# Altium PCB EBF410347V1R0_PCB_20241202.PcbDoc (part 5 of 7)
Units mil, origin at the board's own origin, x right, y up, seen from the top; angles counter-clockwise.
Board outline 5098.43 x 3464.57 mil, 6 copper layers (TOP, GND02, ART03, ART04, PWR05, BOTTOM), stack 47.2 mil thick; 566 components, 452 nets, 1905 pads, 1432 vias.
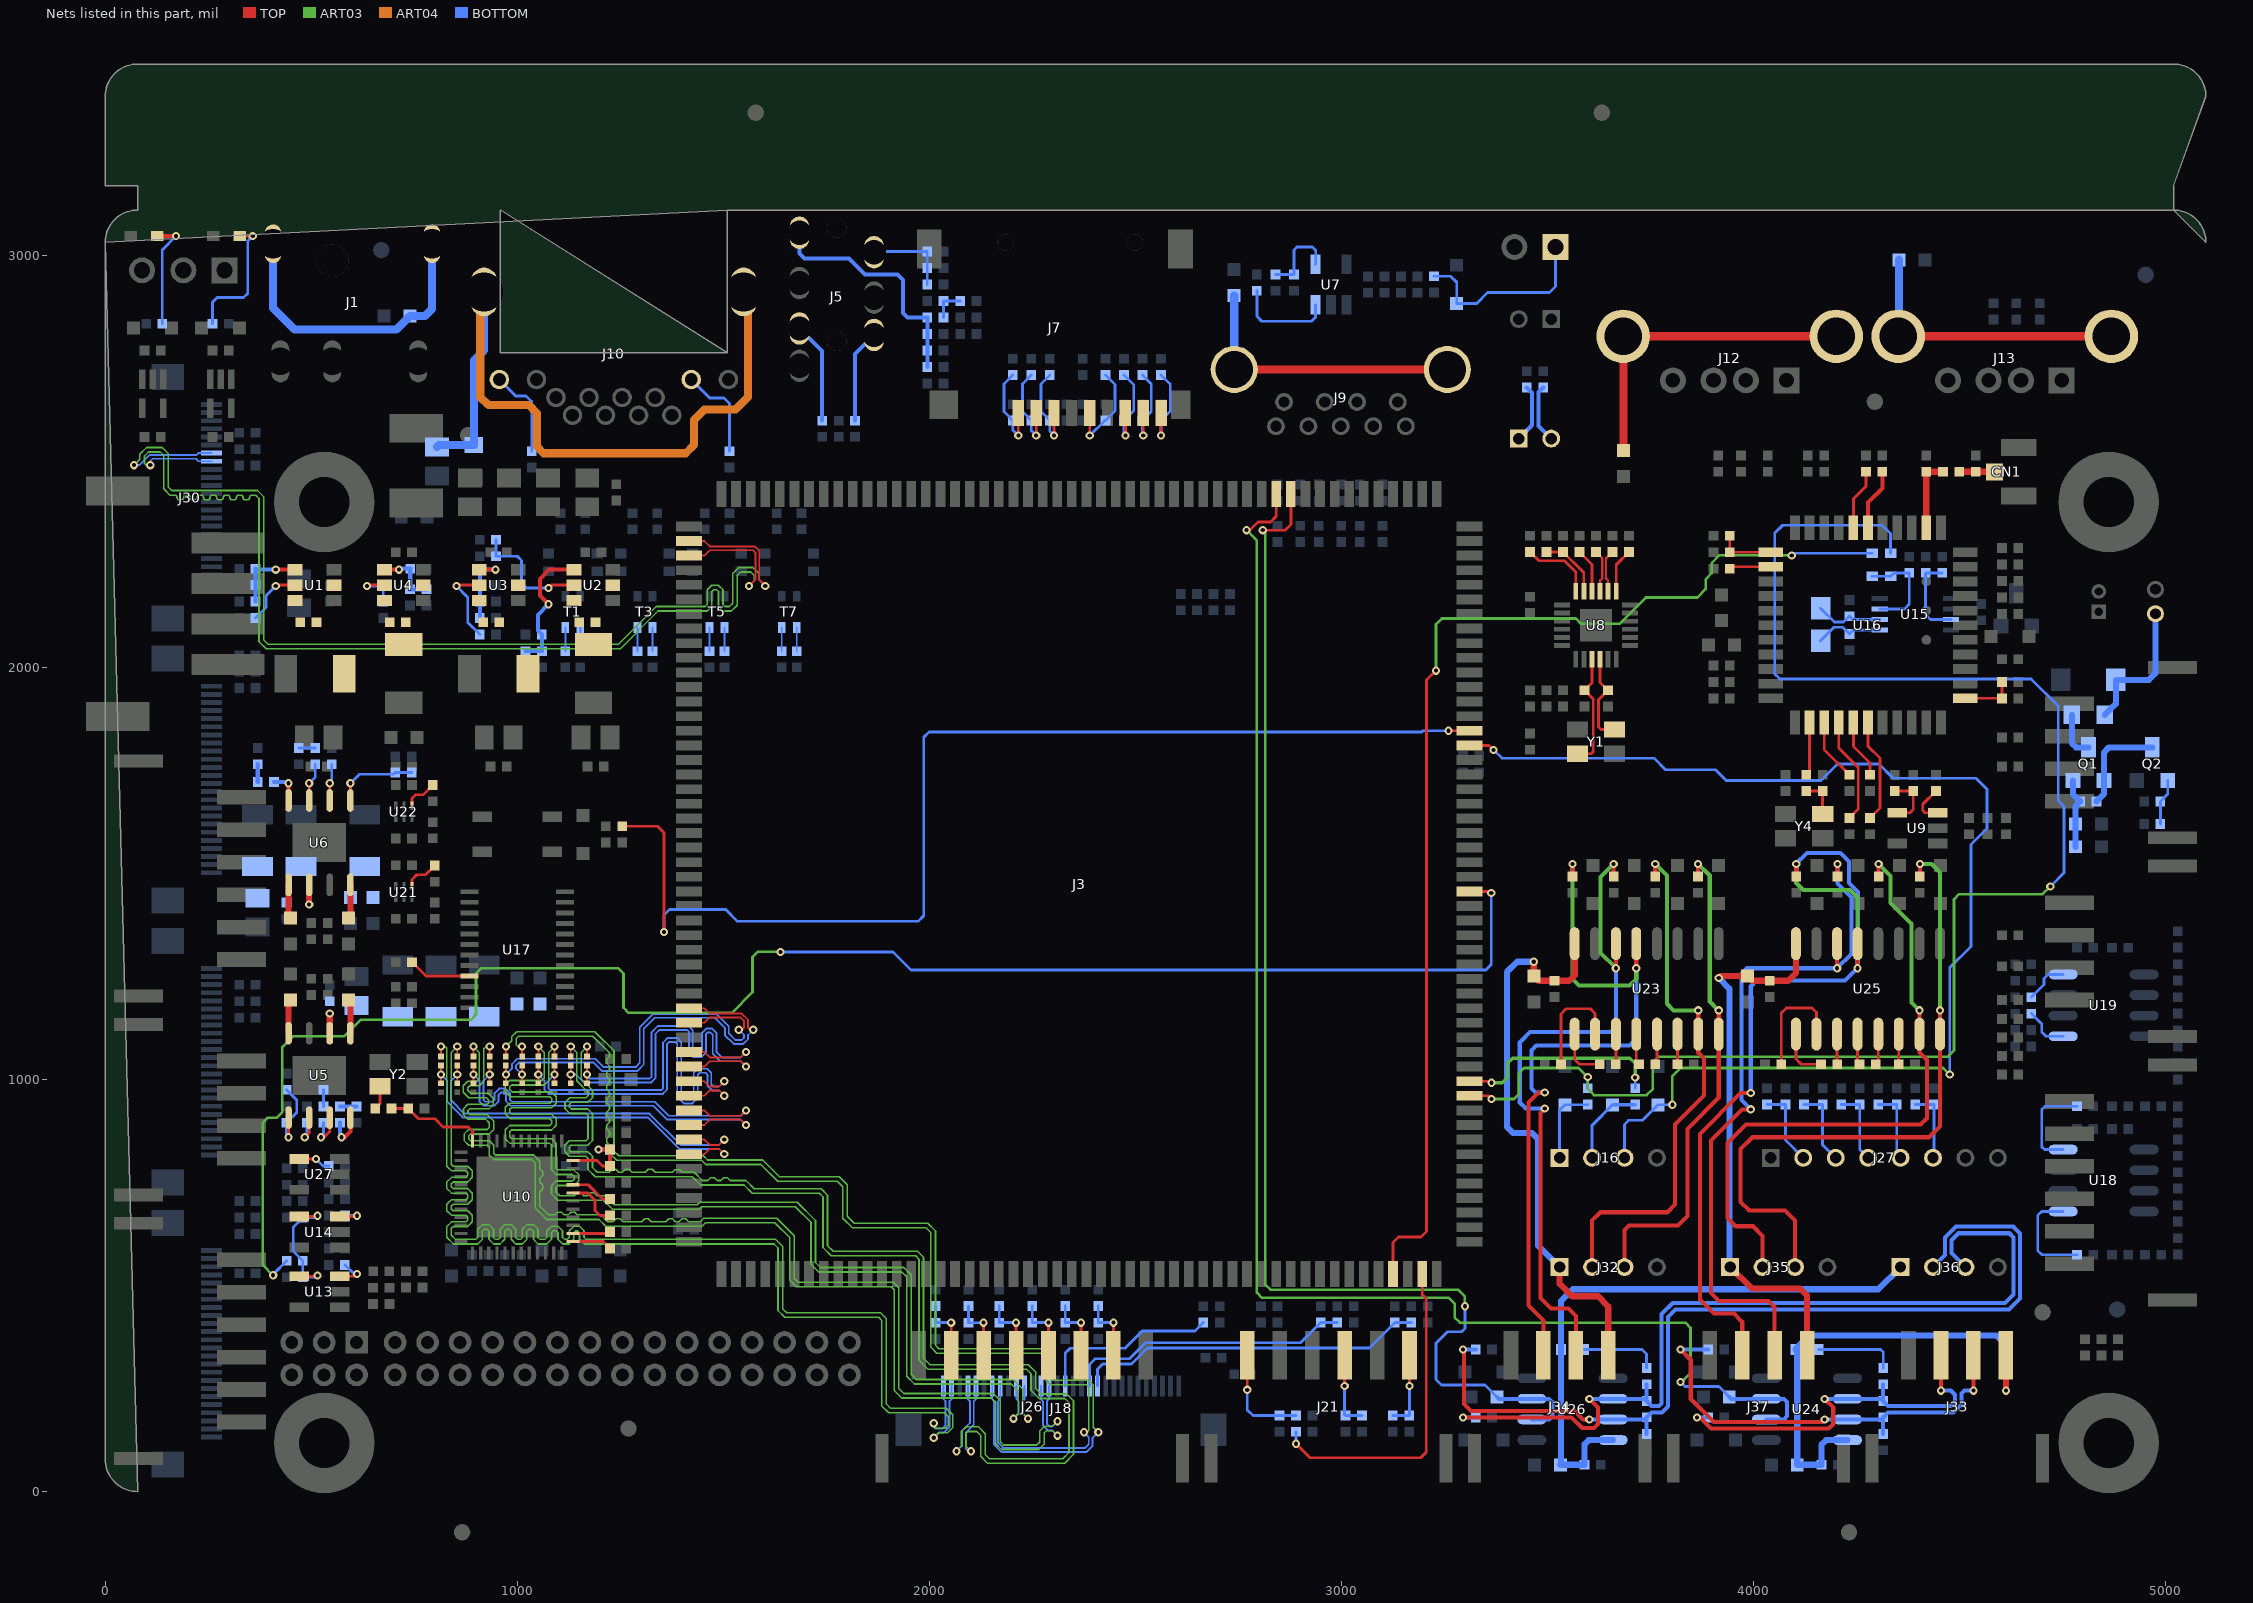
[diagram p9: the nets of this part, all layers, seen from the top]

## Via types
v1: diameter 20, hole 10, TOP to BOTTOM, 1432 vias

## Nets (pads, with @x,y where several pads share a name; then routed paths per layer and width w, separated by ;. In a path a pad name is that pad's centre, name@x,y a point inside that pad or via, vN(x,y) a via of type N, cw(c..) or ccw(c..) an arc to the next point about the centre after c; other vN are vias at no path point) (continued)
MIPI_CSI_RX1_D3N: J3.103 J30.8 | length 2705.2
  TOP w4.5: J3.103@1416.89,2271.61 1454.32,2271.61 1467.29,2284.58 1572.42,2284.58 1578,2279 1578,2213.37 v1(1562.63,2198)
  ART03 w4: v1(109.42,2491.05) 99.35,2491.05 95.24,2495.16 95.24,2513.24 105,2523 134,2523 142,2515 142,2433.64 157.24,2418.4 168.64,2418.4 cw(c168.64,2412.6) 174.44,2412.6 ccw(c180.24,2412.6) 180.24,2406.8 184.64,2406.8 ccw(c184.64,2412.6) 190.44,2412.6 cw(c196.24,2412.6) 196.24,2418.4 200.64,2418.4 cw(c200.64,2412.6) 206.44,2412.6 ccw(c212.24,2412.6) 212.24,2406.8 216.64,2406.8 ccw(c216.64,2412.6) 222.44,2412.6 cw(c228.24,2412.6) 228.24,2418.4 232.64,2418.4 cw(c232.64,2412.6) 238.44,2412.6 ccw(c244.24,2412.6) 244.24,2406.8 248.64,2406.8 ccw(c248.64,2412.6) 254.44,2412.6 cw(c260.24,2412.6) 260.24,2418.4 264.64,2418.4 cw(c264.64,2412.6) 270.44,2412.6 ccw(c276.24,2412.6) 276.24,2406.8 280.64,2406.8 ccw(c280.64,2412.6) 286.44,2412.6 cw(c292.24,2412.6) 292.24,2418.4 296.64,2418.4 cw(c296.64,2412.6) 302.44,2412.6 ccw(c308.24,2412.6) 308.24,2406.8 312.64,2406.8 ccw(c312.64,2412.6) 318.44,2412.6 cw(c324.24,2412.6) 324.24,2418.4 328.64,2418.4 cw(c328.64,2412.6) 334.44,2412.6 ccw(c340.24,2412.6) 340.24,2406.8 344.64,2406.8 ccw(c344.64,2412.6) 350.44,2412.6 cw(c356.24,2412.6) 356.24,2418.4 365.24,2418.4 373.4,2410.24 373.4,2062.8 390.6,2045.6 1250.4,2045.6 1341.8,2137 1461.18,2137 1472.31,2148.13 1472.31,2184.31 1477,2189 1483.63,2189 1488.31,2184.31 1488.31,2148.13 1499.44,2137 1519.56,2137 1534,2151.44 1534,2223.44 1542.19,2231.63 1567,2231.63 1576,2222.63 1576,2211.37 v1(1562.63,2198)
  BOTTOM w4.5: v1(109.42,2491.05) 109.42,2501.15 114.78,2506.5 220.44,2506.5 226.39,2500.55 J30.8@257.91,2500.55
MIPI_CSI_RX1_D3P: J3.102 J30.7 | length 2709
  TOP w4.5: J3.102@1416.89,2307.05 1454.32,2307.05 1467.29,2294.08 1576.36,2294.08 1587.5,2282.94 1587.5,2212.5 v1(1602,2198)
  ART03 w4: v1(70.06,2491.05) 84.24,2505.24 84.24,2517.8 100.44,2534 138.56,2534 153,2519.56 153,2438.2 161.8,2429.4 369.8,2429.4 384.4,2414.8 384.4,2067.36 395.16,2056.6 1245.84,2056.6 1337.24,2148 1456.63,2148 1461.31,2152.69 1461.31,2188.87 1472.44,2200 1488.18,2200 1499.31,2188.87 1499.31,2152.69 1504,2148 1515,2148 1523,2156 1523,2228 1537.63,2242.63 1571.56,2242.63 1587,2227.19 1587,2213 v1(1602,2198)
  BOTTOM w4.5: v1(70.06,2491.05) 83.05,2491.05 108,2516 222.15,2516 226.39,2520.24 J30.7@257.91,2520.24
MIPI_CTP_INT: J18.11 R81.2 R176.2 | length 849.4
  BOTTOM w6.8: J18.11@2408.58,255.91 2408.58,296.98 2421,309.4 2490.71,309.4 2529.71,348.4 3068.08,348.4 R176.2@3130,410.32 R81.2@3170,410.32
MIPI_CTP_RST: J18.12 R177.2 R182.2 | length 695.9
  BOTTOM w6.8: J18.12@2388.89,255.91 2388.89,308.6 2402.49,322.2 2485.4,322.2 2524.4,361.2 2900.88,361.2 R177.2@2950,410.32 R182.2@2990,410.32
MIPI_DSI_CLKN: J18.24 R106.2 | length 2762.8
  TOP w4.5: R106.2@972.48,1055.83 v1(972.48,1080)
  ART03 w4: v1(972.48,1080) 986.66,1094.18 986.66,1104.4 998.64,1116.37 1188.19,1116.37 1235,1069.56 1235,826 1246,815 1451.56,815 1461.89,804.66 1595.89,804.66 1636.56,764 1781.56,764 1801,744.56 1801,668 1818,651 1996.56,651 2015,632.56 2015,355 2023,347 2278,347 2290,335 2290,279.56 2299.56,270 2386,270 2398.25,257.75 2398.25,156.17 v1(2410.29,144.13)
  BOTTOM w4.5: J18.24@2152.67,255.91 2152.67,224.38 2157.5,219.55 2157.5,114.06 2175.06,96.5 2381.94,96.5 2396.5,111.06 2396.5,130.34 v1(2410.29,144.13)
MIPI_DSI_CLKP: J18.23 R105.2 | length 2745.4
  TOP w4.5: R105.2@1011.85,1055.83 v1(1011.85,1080)
  ART03 w4: v1(1011.85,1080) 1001.67,1080 997.66,1084 997.66,1099.84 1003.19,1105.37 1183.63,1105.37 1224,1065 1224,1056 1217,1049 1217,1040 1224,1033 1224,1024 1217,1017 1217,1008 1224,1001 1224,992 1217,985 1217,976 1224,969 1224,960 1217,953 1217,944 1224,937 1224,928 1217,921 1217,912 1224,905 1224,896 1217,889 1217,880 1224,873 1224,864 1217,857 1217,848 1224,841 1224,821.44 1241.44,804 1447,804 1457.34,793.66 1591.34,793.66 1632,753 1777,753 1790,740 1790,663.44 1813.44,640 1992,640 2004,628 2004,350.44 2018.44,336 2273.44,336 2279,330.44 2279,275 2295,259 2381.44,259 2387.25,253.19 2387.25,148.25 2383.13,144.13 v1(2375.21,144.13)
  BOTTOM w4.5: J18.23@2172.36,255.91 2172.36,224.38 2167,219.02 2167,118 2179,106 2378,106 2387,115 2387,132.34 v1(2375.21,144.13)
MIPI_DSI_D0N: J18.27 R88.2 | length 2847.8
  TOP w4.5: R88.2@1129.96,1055.83 v1(1129.96,1080)
  ART03 w4: v1(1129.96,1080) 1144.14,1065.82 1144.14,996.86 1171.63,969.37 1171.63,960.37 1166.94,955.68 1127.13,955.68 1116,944.55 1116,928.81 1127.13,917.68 1166.94,917.68 1171.63,913 1171.63,856.41 1166.94,851.72 1126.13,851.72 1115,840.59 1115,824.85 1126.13,813.72 1166.94,813.72 1171.63,809.04 1171.63,781.81 1189.44,764 1425,764 1445,744 1550.44,744 1570.44,724 1733,724 1742,715 1742,592.44 1762.44,572 1967,572 1975,564 1975,319 1997,297 2236,297 2247,286 2247,246 2267,226 2329,226 2339,216 2339,95 2324,80 2146,80 2136,90 2136,140.56 2119.56,157 2089.44,157 2078.25,145.81 2078.25,110.04 v1(2066.21,98)
  BOTTOM w4.5: v1(2066.21,98) 2079,110.79 2079,147 2098.5,166.5 2098.5,219.5 2093.62,224.38 J18.27@2093.62,255.91
MIPI_DSI_D0P: J18.26 R87.2 | length 2885.6
  TOP w4.5: R87.2@1169.33,1055.83 v1(1169.33,1080)
  ART03 w4: v1(1169.33,1080) 1155.14,1065.82 1155.14,1001.41 1182.63,973.93 1182.63,955.81 1171.5,944.68 1131.69,944.68 1127,940 1127,933.37 1131.69,928.68 1171.5,928.68 1182.63,917.55 1182.63,851.85 1171.5,840.72 1130.69,840.72 1126,836.04 1126,829.41 1130.69,824.72 1171.5,824.72 1182.63,813.59 1182.63,786.37 1194,775 1223.43,775 1230.43,782 1239.43,782 1246.43,775 1255.43,775 1262.43,782 1271.43,782 1278.43,775 1310.69,775 1317.69,782 1327.69,782 1334.69,775 1376.75,775 1382.75,781 1394.75,781 1400.75,775 1429.56,775 1449.56,755 1462.2,755 1469.2,762 1478.2,762 1485.2,755 1494.2,755 1501.2,762 1510.2,762 1517.2,755 1555,755 1575,735 1737.56,735 1753,719.56 1753,597 1767,583 1971.56,583 1986,568.56 1986,323.56 2001.56,308 2240.56,308 2258,290.56 2258,250.56 2271.56,237 2333.56,237 2350,220.56 2350,90.44 2328.56,69 2141.44,69 2125,85.44 2125,136 2115,146 2094,146 2089.25,141.25 2089.25,110.04 v1(2101.29,98)
  BOTTOM w4.5: v1(2101.29,98) 2095,98 2088.5,104.5 2088.5,143.06 2108,162.56 2108,219.08 2113.3,224.38 J18.26@2113.3,255.91
MIPI_DSI_D1N: J18.21 R92.2 | length 2775.8
  TOP w4.5: R92.2@1051.22,1055.83 v1(1051.22,1080)
  ART03 w4: v1(1051.22,1080) 1065.4,1065.82 1065.4,1002.31 1060.72,997.62 982.13,997.62 971,986.49 971,970.75 983.13,958.62 1078.72,958.62 1083.4,953.94 1083.4,947.31 1078.72,942.62 981.13,942.62 971,932.49 971,916.75 983.13,904.62 1078.72,904.62 1083.4,899.94 1083.4,893.31 1078.72,888.62 981.44,888.62 971,878.18 971,856.44 982.44,845 1079,845 1083,841 1083,780.82 1094.13,769.69 1133.31,769.69 1138,765 1138,758.37 1133.31,753.69 1094.13,753.69 1083,742.56 1083,722.44 1098.44,707 1209,707 1231,685 1441.56,685 1448.05,691.5 1674.95,691.5 1713,653.44 1713,551.44 1731.44,533 1933.44,533 1945,521.44 1945,280 1964,261 2199,261 2216.25,243.75 2216.25,189.04 v1(2204.21,177)
  BOTTOM w4.5: v1(2204.21,177) 2217,189.79 2217,219.11 2211.73,224.38 J18.21@2211.73,255.91
MIPI_DSI_D1P: J18.20 R91.2 | length 2787
  TOP w4.5: R91.2@1090.59,1055.83 v1(1090.59,1080)
  ART03 w4: v1(1090.59,1080) 1076.4,1065.82 1076.4,997.75 1065.28,986.62 986.69,986.62 982,981.94 982,975.31 987.69,969.62 1083.28,969.62 1094.4,958.49 1094.4,942.75 1083.28,931.62 986,931.62 982,927.62 982,921.31 987.69,915.62 1083.28,915.62 1094.4,904.49 1094.4,888.75 1083.28,877.62 986,877.62 982,873.62 982,861 987,856 1083.56,856 1094,845.56 1094,785.37 1098.69,780.69 1137.87,780.69 1149,769.56 1149,753.82 1137.87,742.69 1098.69,742.69 1094,738 1094,727 1103,718 1138.7,718 1145.7,725 1154.7,725 1161.7,718 1170.7,718 1177.7,725 1186.7,725 1193.7,718 1213.56,718 1235.56,696 1437,696 1443.5,702.5 1679.5,702.5 1724,658 1724,556 1736,544 1938,544 1956,526 1956,284.56 1968.56,272 2203.56,272 2227.25,248.31 2227.25,189.04 v1(2239.29,177)
  BOTTOM w4.5: J18.20@2231.41,255.91 2231.41,224.38 2226.5,219.47 2226.5,189.79 v1(2239.29,177)
MIPI_DSI_D2N: J18.18 R96.2 | length 2773
  TOP w4.5: R96.2@893.74,1055.83 v1(893.74,1080)
  ART03 w4: v1(893.74,1080) 907.92,1065.82 907.92,1000.76 903.24,996.07 879.91,996.07 868.78,984.94 868.78,969.2 882.26,955.73 925.34,955.73 931.03,950.04 931.03,943.73 927.03,939.73 879.91,939.73 869.47,929.28 869.47,914.51 879.91,904.07 922.93,904.07 932,895 932,883.52 927.31,878.84 882.13,878.84 871,867.71 871,851.97 882.13,840.84 927.31,840.84 932,836.15 932,816.44 942.44,806 1035.44,806 1044,797.44 1044,688.44 1071.97,660.47 1198.53,660.47 1215,644 1448.56,644 1456.68,652.13 1625.32,652.13 1661,616.44 1661,513.44 1677.44,497 1908,497 1915,490 1915,245.44 1933.44,227 2151,227 2161,217 2161,116.44 2175.44,102 2265.56,102 2279,115.44 2279,142.44 2284.31,147.75 2299.09,147.75 v1(2311.13,135.71)
  BOTTOM w4.5: J18.18@2270.78,255.91 2270.78,224.38 2275.87,219.29 2275.87,160.69 2288.06,148.5 2298.34,148.5 v1(2311.13,135.71)
MIPI_DSI_D2P: J18.17 R95.2 | length 2790
  TOP w4.5: R95.2@933.11,1055.83 v1(933.11,1080)
  ART03 w4: v1(933.11,1080) 924,1080 918.92,1074.92 918.92,996.2 907.8,985.07 884.47,985.07 879.78,980.38 879.78,973.76 886.81,966.73 929.9,966.73 942.03,954.6 942.03,939.17 931.58,928.73 884.47,928.73 880.47,924.73 880.47,919.07 884.47,915.07 927.49,915.07 943,899.56 943,878.97 931.87,867.84 886.69,867.84 882,863.15 882,856.52 886.69,851.84 931.87,851.84 943,840.71 943,821 947,817 1040,817 1055,802 1055,782.92 1062,775.92 1062,766.92 1055,759.92 1055,750.92 1062,743.92 1062,734.92 1055,727.92 1055,693 1076.53,671.47 1091.4,671.47 1097.93,678 1107.4,678 1113.93,671.47 1123.4,671.47 1129.93,678 1139.4,678 1145.93,671.47 1203.09,671.47 1219.56,655 1232.53,655 1239.53,662 1249.53,662 1256.53,655 1302.16,655 1309.16,662 1318.16,662 1325.16,655 1360.78,655 1367.78,662 1376.78,662 1383.78,655 1392.78,655 1399.78,662 1408.78,662 1415.78,655 1444,655 1452.13,663.13 1629.87,663.13 1672,621 1672,518 1682,508 1912.56,508 1926,494.56 1926,250 1938,238 2155.56,238 2172,221.56 2172,121 2180,113 2261,113 2268,120 2268,147 2279.75,158.75 2299.09,158.75 v1(2311.13,170.79)
  BOTTOM w4.5: J18.17@2290.47,255.91 2290.47,224.38 2285.37,219.29 2285.37,164.63 2292,158 2298.34,158 v1(2311.13,170.79)
MIPI_DSI_D3N: J18.30 R101.2 | length 2813.8
  TOP w4.5: R101.2@815,1055.83 v1(815,1080)
  ART03 w4: v1(815,1080) 825.18,1080 829.18,1076 829.18,789.59 840.31,778.47 875.31,778.47 880,773.78 880,767.15 875.31,762.47 840.31,762.47 829.18,751.34 829.18,735.59 840.31,724.47 875.31,724.47 880,719.78 880,713.15 875.31,708.47 840.31,708.47 829.18,697.34 829.18,681.59 840.31,670.47 875.31,670.47 880,665.78 880,659.15 875.31,654.47 840.31,654.47 829.18,643.34 829.18,617.26 845.44,601 904.36,601 915.49,612.13 915.49,632.31 920.18,637 926.8,637 931.49,632.31 931.49,612.13 942.62,601 958.36,601 969.49,612.13 969.49,632.31 974.18,637 980.8,637 985.49,632.31 985.49,612.13 996.62,601 1012.36,601 1023.49,612.13 1023.49,632.31 1028.18,637 1034.81,637 1039.49,632.31 1039.49,612.13 1050.62,601 1071.85,601 1082.98,612.13 1082.98,628.19 1087.67,632.87 1094.29,632.87 1098.98,628.19 1098.98,612.13 1110.11,601 1125.85,601 1136.98,612.13 1136.98,628.19 1141.35,632.55 1147,632.55 1151,628.55 1151,612.44 1162.44,601 1623,601 1633,591 1633,439.44 1649.44,423 1877,423 1885,415 1885,207.84 1901.44,191.4 2036.6,191.4 2046.17,181.83 2046.17,160.17 2039.75,153.75 2014.87,153.75 2010.87,157.75 v1(2010.87,165.79)
  BOTTOM w4.5: v1(2010.87,165.79) 2010.87,159.13 2017,153 2032,153 2039.5,160.5 2039.5,219.44 2034.56,224.38 J18.30@2034.56,255.91
MIPI_DSI_D3P: J18.29 R100.2 | length 2833.4
  TOP w4.5: R100.2@854.37,1055.83 v1(854.37,1080)
  ART03 w4: v1(854.37,1080) 840.18,1065.82 840.18,794.15 844.87,789.47 879.87,789.47 891,778.34 891,762.59 879.87,751.47 844.87,751.47 840.18,746.78 840.18,740.15 844.87,735.47 879.87,735.47 891,724.34 891,708.59 879.87,697.47 844.87,697.47 840.18,692.78 840.18,686.15 844.87,681.47 879.87,681.47 891,670.34 891,654.59 879.87,643.47 844.87,643.47 840.18,638.78 840.18,621.82 850,612 899.8,612 904.49,616.69 904.49,636.87 915.62,648 931.36,648 942.49,636.87 942.49,616.69 947.18,612 953.8,612 958.49,616.69 958.49,636.87 969.62,648 985.36,648 996.49,636.87 996.49,616.69 1001.18,612 1007.8,612 1012.49,616.69 1012.49,636.87 1023.62,648 1039.36,648 1050.49,636.87 1050.49,616.69 1055.18,612 1067.29,612 1071.98,616.69 1071.98,632.74 1083.11,643.87 1098.85,643.87 1109.98,632.74 1109.98,616.69 1114.67,612 1121.29,612 1125.98,616.69 1125.98,632.74 1136.79,643.55 1151.56,643.55 1162,633.11 1162,617 1167,612 1627.56,612 1644,595.56 1644,444 1654,434 1881.56,434 1896,419.56 1896,212.4 1906,202.4 2041.16,202.4 2057.17,186.39 2057.17,155.61 2044.31,142.75 2022.91,142.75 v1(2010.87,130.71)
  BOTTOM w4.5: v1(2010.87,130.71) 2023.66,143.5 2035.93,143.5 2049,156.56 2049,219.13 2054.25,224.38 J18.29@2054.25,255.91
MIPI_DSI_TX_CLKN: J3.135 R106.1 R107.1 | length 992.5
  TOP w4.5: R107.1@972.48,990.83 v1(972.48,1012.5) R106.1@972.48,1034.17 ; J3.135@1416.89,1137.76 1454.32,1137.76 1467.29,1150.72 1540.84,1150.72 1550.5,1141.06 1550.5,1125.44 1546,1120.94 v1(1537.71,1120.94)
  BOTTOM w4.5: v1(972.48,1012.5) 987.41,1027.43 987.41,1037.73 1000.18,1050.5 1189.5,1050.5 1209.84,1030.16 1287.16,1030.16 1297.5,1040.5 1297.5,1126.94 1330.06,1159.5 1483.5,1159.5 1513.5,1129.5 1513.5,1111.94 1529.44,1096 1544.72,1096 1550.5,1101.78 1550.5,1108.14 v1(1537.71,1120.94)
MIPI_DSI_TX_CLKP: J3.134 R104.1 R105.1 | length 1008.2
  TOP w4.5: R104.1@1011.85,990.83 v1(1011.85,1012.5) R105.1@1011.85,1034.17 ; J3.134@1416.89,1173.19 1454.32,1173.19 1467.29,1160.22 1544.78,1160.22 1560,1145 1560,1125.44 1564.5,1120.94 v1(1572.79,1120.94)
  BOTTOM w4.5: v1(1011.85,1012.5) 996.91,1027.43 996.91,1033.8 1004.12,1041 1185.56,1041 1205.9,1020.66 1291.1,1020.66 1307,1036.57 1307,1123 1334,1150 1479.56,1150 1504,1125.56 1504,1108 1525.5,1086.5 1548.66,1086.5 1560,1097.84 1560,1108.14 v1(1572.79,1120.94)
MIPI_DSI_TX_D0N: J3.138 R88.1 R89.1 | length 910
  TOP w4.5: R89.1@1129.96,990.83 v1(1129.96,1012.5) R88.1@1129.96,1034.17 ; J3.138@1416.89,1031.46 1454.32,1031.46 1467.29,1044.42 1542.21,1044.42 v1(1555,1031.63)
  BOTTOM w4.5: v1(1129.96,1012.5) 1141.39,1012.5 1160.82,993.07 1325.44,993.07 1335.5,1003.13 1335.5,1110.5 1345.57,1120.57 1412,1120.57 1416.5,1116.07 1416.5,1065.06 1426.56,1055 1447.94,1055 1458,1065.06 1458,1109.63 1462.64,1114.27 1469,1114.27 1474.5,1108.77 1474.5,1062.39 1492.47,1044.42 1542.21,1044.42 v1(1555,1031.63)
MIPI_DSI_TX_D0P: J3.137 R86.1 R87.1 | length 869.9
  TOP w4.5: R86.1@1169.33,990.83 v1(1169.33,1012.5) R87.1@1169.33,1034.17 ; J3.137@1416.89,1066.89 1454.32,1066.89 1467.29,1053.92 1542.21,1053.92 v1(1555,1066.71)
  BOTTOM w4.5: v1(1169.33,1012.5) 1169.33,1007.07 1173.83,1002.57 1321.5,1002.57 1326,1007.07 1326,1114.44 1341.63,1130.07 1415.94,1130.07 1426,1120 1426,1069 1430.5,1064.5 1444,1064.5 1448.5,1069 1448.5,1113.57 1458.7,1123.77 1472.94,1123.77 1484,1112.71 1484,1066.33 1496.4,1053.92 1542.21,1053.92 v1(1555,1066.71)
MIPI_DSI_TX_D1N: J3.140 R92.1 R93.1 | length 981.6
  TOP w4.5: R93.1@1051.22,990.83 v1(1051.22,1012.5) R92.1@1051.22,1034.17 ; J3.140@1416.89,960.59 1454.32,960.59 1467.29,973.56 1489.62,973.56 v1(1502.41,960.77)
  BOTTOM w4.5: v1(1051.22,1012.5) 1066.15,997.57 1066.15,975.06 1076.22,965 1353.44,965 1363.5,975.06 1363.5,1086 1369,1091.5 1384,1091.5 1388.5,1087 1388.5,958.06 1404.56,942 1425,942 1438.07,955.06 1438.07,1012.07 1442.57,1016.57 1457,1016.57 1461.5,1012.07 1461.5,985.12 1473.06,973.56 1489.62,973.56 v1(1502.41,960.77)
MIPI_DSI_TX_D1P: J3.139 R90.1 R91.1 | length 965.9
  TOP w4.5: R90.1@1090.59,990.83 v1(1090.59,1012.5) R91.1@1090.59,1034.17 ; J3.139@1416.89,996.02 1454.32,996.02 1467.29,983.06 1489.62,983.06 v1(1502.41,995.85)
  BOTTOM w4.5: v1(1090.59,1012.5) 1075.65,997.57 1075.65,979 1080.15,974.5 1349.5,974.5 1354,979 1354,1089.94 1365.06,1101 1387.94,1101 1398,1090.94 1398,962 1408.5,951.5 1421.07,951.5 1428.57,959 1428.57,1016 1438.63,1026.07 1460.94,1026.07 1471,1016 1471,989.06 1477,983.06 1489.62,983.06 v1(1502.41,995.85)
MIPI_DSI_TX_D2N: J3.142 R96.1 R97.1 | length 979.2
  TOP w4.5: R97.1@893.74,990.83 v1(893.74,1012.5) R96.1@893.74,1034.17 ; J3.142@1416.89,889.72 1454.32,889.72 1467.29,902.69 1542.21,902.69 v1(1555,889.9)
  BOTTOM w4.5: v1(893.74,1012.5) 908.67,997.57 908.67,946.56 918.74,936.5 943.85,936.5 954.69,947.34 954.69,963.23 959.96,968.5 967.41,968.5 972.69,963.23 972.69,947.34 983.52,936.5 1330.06,936.5 1363.81,902.75 1542.15,902.75 v1(1555,889.9)
MIPI_DSI_TX_D2P: J3.141 R94.1 R95.1 | length 963.4
  TOP w4.5: R94.1@933.11,990.83 v1(933.11,1012.5) R95.1@933.11,1034.17 ; J3.141@1416.89,925.16 1454.32,925.16 1467.29,912.19 1542.21,912.19 v1(1555,924.98)
  BOTTOM w4.5: v1(933.11,1012.5) 918.17,997.57 918.17,950.5 922.67,946 939.91,946 945.19,951.27 945.19,967.16 956.02,978 971.35,978 982.19,967.16 982.19,951.27 987.46,946 1334,946 1367.75,912.25 1542.27,912.25 v1(1555,924.98)
MIPI_DSI_TX_D3N: J3.144 R101.1 R102.1 | length 937.5
  TOP w4.5: R102.1@815,990.83 v1(815,1012.5) R101.1@815,1034.17 ; J3.144@1416.89,818.86 1454.32,818.86 1467.29,831.83 1489.62,831.83 v1(1502.41,819.03)
  BOTTOM w4.5: v1(815,1012.5) 829.93,997.57 829.93,945.63 867.56,908 1317,908 1393.18,831.82 1489.62,831.82 v1(1502.41,819.03)
MIPI_DSI_TX_D3P: J3.143 R99.1 R100.1 | length 921.8
  TOP w4.5: R99.1@854.37,990.83 v1(854.37,1012.5) R100.1@854.37,1034.17 ; J3.143@1416.89,854.29 1454.32,854.29 1467.29,841.33 1489.62,841.33 v1(1502.41,854.12)
  BOTTOM w4.5: v1(854.37,1012.5) 839.43,997.57 839.43,949.56 871.5,917.5 1320.94,917.5 1397.11,841.32 1489.62,841.32 v1(1502.41,854.12)
MIPI_LCD_PWR_EN: J3.25 R179.1 | length 4173.7
  TOP w6.8: J3.25@3310.59,1456.65 3360.06,1456.65 v1(3364,1452.72)
  ART03 w6.3: v1(407.72,525) 382,550.72 382,895 394,907 416,907 430,921 430,1079 456,1105 580,1105 620,1145 887.4,1145 900,1157.6 900,1257.4 912.6,1270 1245.4,1270 1258,1257.4 1258,1174.6 1270.6,1162 1521,1162 1571,1212 1571,1297.14 1583.6,1309.74 v1(1639,1309.74)
  BOTTOM w6.8: v1(407.72,525) 407.72,527.4 R179.1@440.32,560 ; v1(1639,1309.74) 1912.26,1309.74 1956,1266 3350.4,1266 3364,1279.6 v1(3364,1452.72)
MIPI_LCD_RST: J18.15 R186.2 | length 445.9
  BOTTOM w6.8: J18.15@2329.84,255.91 2329.84,335.84 2342,348 2475,348 2517,390 2644.68,390 R186.2@2665,410.32
N16722097: C10.1 U2.6
N16722109: C10.2 L3.1 U2.2
N16722129: C12.1 R5.1 R9.1 U2.4 | length 331
  TOP w10: v1(1076,2153.63) 1055,2174.63 1055,2215 1077.4,2237.4 U2.4@1137.76,2237.4
  BOTTOM w10: R5.1@1020,2039.68 C12.1@1060,2039.68 1059.68,2040 R9.1@1059.68,2080 1050,2089.68 1050,2127.63 v1(1076,2153.63)
N16722243: R7.1 R8.1 U2.5 | length 296.1
  TOP w6.8: v1(1076,2193) 1083,2200 U2.5@1137.76,2200
  BOTTOM w6.8: R8.1@948.68,2310 R7.1@948.68,2270 1000,2270 1010,2260 1010,2204.97 1021.97,2193 v1(1076,2193)
N16722849: J1.1 J1.5 L2.1 | length 742.8
  BOTTOM w20: J1.1@407.48,3028.61 407.48,2872.52 460,2820 706.5,2820 L2.1@739.5,2853 776,2853 793.28,2870.28 J1.5@793.28,3028.61
N16722969: C25.1 R14.1 R17.1 U4.4 | length 154.1
  TOP w10: U4.4@677.76,2237.4 v1(713,2237.4)
  BOTTOM w10: v1(713,2237.4) 715.6,2240 R17.1@740.32,2240 740.32,2190 R14.1@740,2189.68 C25.1@780,2189.68
N16722987: C22.2 L5.1 U4.2
N16723079: C22.1 U4.6
N16723587: C1.1 U1.6
N16723611: C1.2 L1.1 U1.2
N16723631: C2.1 R1.1 R4.1 U1.4 | length 177.2
  TOP w10: v1(413.82,2237.4) U1.4@460.76,2237.4
  BOTTOM w10: R1.1@364.68,2160 C2.1@364.68,2200 R4.1@364.68,2240 367.28,2237.4 v1(413.82,2237.4)
N16724039: R10.1 U3.5 | length 197.6
  TOP w6.8: v1(852.52,2198.03) 854.49,2200 U3.5@907.76,2200
  BOTTOM w6.8: v1(852.52,2198.03) 852.52,2197.48 880,2170 880,2109.32 R10.1@909.32,2080
N16724119: C11.1 U3.6
N16724131: C11.2 L4.1 U3.2
N16724163: C15.1 R6.1 R11.1 U3.4 | length 189.6
  TOP w10: U3.4@907.76,2237.4 v1(947,2237.4)
  BOTTOM w10: C15.1@909.32,2120 R6.1@909.32,2160 R11.1@909.32,2200 909.32,2229.32 917.4,2237.4 v1(947,2237.4)
N16724623: LED2.2 R13.2 | length 323
  TOP w6.8: LED2.2@326.19,3047.24 v1(358.24,3047.24)
  BOTTOM w6.8: R13.2@260.32,2834.37 260.32,2886.32 272,2898 336,2898 346,2908 346,3035 v1(358.24,3047.24)
N16724791: LED1.2 R12.2 | length 272.5
  TOP w10: LED1.2@126.19,3047.24 v1(172,3047.24)
  BOTTOM w6.8: R12.2@138.68,2834.37 138.68,3013.92 v1(172,3047.24)
N16783121: D7.1 J7.1 R43.2 | length 225
  TOP w6.8: v1(2216.15,2563) J7.1@2216.15,2618.11
  BOTTOM w6.8: R43.2@2202.61,2709.69 2181.41,2688.49 2181.41,2620.89 D7.1@2202.61,2599.69 2202.61,2576.54 v1(2216.15,2563)
N16783123: D3.1 J7.7 R47.2 | length 222.9
  TOP w6.8: v1(2476,2563) J7.7@2475.99,2618.11
  BOTTOM w6.8: R47.2@2472.61,2709.69 2496.41,2685.89 2496.41,2623.49 D3.1@2472.61,2599.69 2472.61,2566.39 v1(2476,2563)
N16783125: D4.1 J7.5 R46.2 | length 237.6
  TOP w6.8: v1(2389.38,2563) J7.5@2389.38,2618.11
  BOTTOM w6.8: v1(2389.38,2563) 2426.07,2599.69 D4.1@2427.61,2599.69 2450.61,2622.69 2450.61,2686.69 R46.2@2427.61,2709.69
N16783127: D5.1 J7.3 R45.2 | length 223.9
  TOP w6.8: v1(2302.77,2563) J7.3@2302.76,2618.11
  BOTTOM w6.8: R45.2@2292.61,2709.69 2270.97,2688.05 2270.97,2621.33 D5.1@2292.61,2599.69 2292.61,2573.16 v1(2302.77,2563)
N16783129: D6.1 J7.2 R44.2 | length 224.3
  TOP w6.8: v1(2259.46,2563) J7.2@2259.46,2618.11
  BOTTOM w6.8: R44.2@2247.61,2709.69 2226.41,2688.49 2226.41,2620.89 D6.1@2247.61,2599.69 2247.61,2574.85 v1(2259.46,2563)
N16783131: D2.1 J7.8 R48.2 | length 220.1
  TOP w6.8: v1(2519.3,2563) J7.8@2519.3,2618.11
  BOTTOM w6.8: R48.2@2517.61,2709.69 2538.81,2688.49 2538.81,2620.89 D2.1@2517.61,2599.69 2517.61,2564.69 v1(2519.3,2563)
N16783147: D1.1 J7.9 R49.2 | length 220
  TOP w6.8: v1(2562.61,2563) J7.9@2562.61,2618.11
  BOTTOM w6.8: v1(2562.61,2563) D1.1@2562.61,2599.69 2584.61,2621.69 2584.61,2687.69 R49.2@2562.61,2709.69
N16783231: J6.1 R41.2 | length 142.9
  BOTTOM w10: J6.1@3430.63,2555.55 3463,2587.92 3463,2666.69 R41.2@3450,2679.69
N16783233: J6.2 R42.2 | length 141.3
  BOTTOM w10: R42.2@3490,2679.69 3479,2668.69 3479,2585.92 J6.2@3509.37,2555.55
N16783279: C28.1 C29.1 C30.1 C31.1 C32.1 R19.2 R21.2 U5.6 | length 47.6
  TOP w15: U5.6@545,1112.36 v1(545,1160)
N16783471: C41.1 C42.1 C43.1 C44.1 C45.1 R30.2 R32.2 U6.6 | length 47.6
  TOP w15: v1(495,1425) U6.6@495,1472.64
N16783658: R25.2 R28.1 U5.1 | length 185.9
  TOP w6.8: v1(445,860) U5.1@445,907.64
  BOTTOM w6.8: R28.1@440,975.32 465,950.32 465,920 440.32,895.32 R25.2@440,895.32 440,865 v1(445,860)
N16783744: R22.2 U5.4 | length 97.6
  TOP w10: v1(573.74,860) 581,860 595,874 U5.4@595,907.64
  BOTTOM w10: R22.2@570,895.32 570,863.74 v1(573.74,860)
N16783769: R24.2 U5.3 | length 98.8
  TOP w6.8: v1(523.74,860) 531.4,860 545,873.6 U5.3@545,907.64
  BOTTOM w6.8: v1(523.74,860) 530,866.26 R24.2@530,895.32
N16783771: C34.2 R22.1 | length 40
  BOTTOM w10: R22.1@570,934.68 C34.2@610,934.68
N16783785: C35.2 R24.1 | length 40.6
  BOTTOM w6.8: R24.1@530,934.68 C35.2@530,975.32
N16783804: L7.1 U5.8 | length 83.2
  TOP w15: U5.8@445,1112.36 445,1188.5 L7.1@450,1193.5
N16783806: L6.1 U5.5 | length 83.2
  TOP w15: L6.1@590,1193.5 595,1188.5 U5.5@595,1112.36
N16783823: C39.1 U5.2 | length 89.7
  TOP w6.8: v1(484.37,860) 495,870.63 U5.2@495,907.64
  BOTTOM w6.8: v1(484.37,860) 490,865.63 C39.1@490,895.32
N16783940: R39.2 R40.1 U6.1 | length 201.5
  TOP w6.8: U6.1@595,1677.36 v1(595,1719)
  BOTTOM w6.8: v1(595,1719) 617,1741 699.68,1741 R40.1@704,1745.32 R39.2@744,1745.32
N16784027: R35.2 U6.4 | length 78.2
  TOP w10: U6.4@445,1677.36 v1(445,1719)
  BOTTOM w10: R35.2@409.68,1722 442,1722 v1(445,1719)
N16784039: R37.2 U6.3 | length 94.2
  TOP w6.8: U6.3@495,1677.36 v1(495,1719)
  BOTTOM w6.8: v1(495,1719) 510,1734 R37.2@510,1765.32
N16784051: C46.2 R35.1 | length 43.5
  BOTTOM w10: C46.2@370,1765.32 370.32,1765 R35.1@370.32,1722
N16784053: C47.2 R37.1 | length 40
  BOTTOM w6.8: C47.2@470,1804.68 R37.1@510,1804.68
N16784084: L9.1 U6.8 | length 83.2
  TOP w15: L9.1@590,1391.5 595,1396.5 U6.8@595,1472.64
N16784086: L8.1 U6.5 | length 83.2
  TOP w15: U6.5@445,1472.64 445,1396.5 L8.1@450,1391.5
N16784100: C51.1 U6.2 | length 90
  TOP w6.8: U6.2@545,1677.36 v1(545,1719)
  BOTTOM w6.8: v1(545,1719) 550,1724 C51.1@550,1765.32
N16784225: C50.1 J5.6 R31.1 R36.1 | length 210
  BOTTOM w6.8: J5.6@1865.98,3007.87 1867.48,3009.37 C50.1@1995.32,3009.37 R31.1@1995.32,2969.37 R36.1@1995.32,2929.37
N16784316: C36.1 J5.1 R20.2 R23.1 R26.1 | length 592.2
  BOTTOM w10: J5.1@1684.88,3055.12 1684.88,3004.49 1697,2992.37 1805,2992.37 1844,2953.37 1923,2953.37 1936,2940.37 1936,2860.37 1947,2849.37 R20.2@1995.32,2849.37 R26.1@1995.32,2809.37 C36.1@1995.32,2769.37 R23.1@1995.32,2729.37
N16784333: C33.1 R18.1 R20.1 | length 80.6
  BOTTOM w6.8: R20.1@2034.68,2849.37 C33.1@2034.68,2889.37 R18.1@2075.32,2889.37
N16784429: J5.3 R34.1 | length 246.6
  BOTTOM w10: J5.3@1684.88,2822.83 1740,2767.72 R34.1@1740,2599.05
N16784431: J5.4 R33.1 | length 227.1
  BOTTOM w10: R33.1@1820,2599.05 1820,2761.1 J5.4@1865.98,2807.09
N16786732: R2.1 R3.1 U4.5 | length 123.8
  TOP w6.8: v1(635.67,2198.03) 637.64,2200 U4.5@677.76,2200
  BOTTOM w6.8: v1(635.67,2198.03) 672.71,2198.03 R2.1@675,2200.32 R3.1@675,2159.68
N16786936: R15.1 U1.5 | length 146.1
  TOP w6.8: v1(413.82,2198.03) 415.79,2200 U1.5@460.76,2200
  BOTTOM w6.8: R15.1@364.68,2120 390,2145.32 390,2174.21 v1(413.82,2198.03)
N16788412: C54.2 T1.4 | length 57.4
  BOTTOM w4.5: C54.2@1116.79,2039.68 T1.4@1116.79,2097.11
N16788414: C55.2 T1.1 | length 57.4
  BOTTOM w4.5: C55.2@1153.21,2039.68 T1.1@1153.21,2097.11
N16788463: C56.2 T3.4 | length 57.4
  BOTTOM w4.5: C56.2@1291.79,2039.68 T3.4@1291.79,2097.11
N16788475: C57.2 T3.1 | length 57.4
  BOTTOM w4.5: C57.2@1328.21,2039.68 T3.1@1328.21,2097.11
N16788524: C58.2 T5.4 | length 57.4
  BOTTOM w4.5: C58.2@1466.79,2039.68 T5.4@1466.79,2097.11
N16788526: C59.2 T5.1 | length 57.4
  BOTTOM w4.5: C59.2@1503.21,2039.68 T5.1@1503.21,2097.11
N16788585: C60.2 T7.4 | length 57.4
  BOTTOM w4.5: C60.2@1641.79,2039.68 T7.4@1641.79,2097.11
N16788587: C61.2 T7.1 | length 57.4
  BOTTOM w4.5: C61.2@1678.21,2039.68 T7.1@1678.21,2097.11
N16792936: J10.9 R16.1 | length 221.3
  BOTTOM w6.8: J10.9@956.57,2698.82 996.39,2659 1021.4,2659 1035,2645.4 R16.1@1035,2524.68
N16792940: C62.2 J10.13 J10.14 R51.2 | length 1838.1
  ART04 w20: J10.13@919.56,2911.42 910,2901.86 910,2657 930,2637 1028,2637 1048,2617 1048,2536 1064,2520 1409,2520 1429,2540 1429,2601 1454,2626 1530,2626 1560,2656 1560,2900.9 J10.14@1549.48,2911.42
  BOTTOM w20: C62.2@805,2535.04 809.96,2540 R51.2@895,2540 895,2745 919.56,2769.56 J10.13@919.56,2911.42
N16793616: J10.11 R50.1 | length 232.6
  BOTTOM w6.8: J10.11@1422.32,2698.82 1467.14,2654 1501.4,2654 1515,2640.4 R50.1@1515,2524.68
N16801073: J9.10 J9.11 L10.2 | length 697
  TOP w20: J9.11@2740.19,2723.24 J9.10@3257.51,2723.24
  BOTTOM w20: L10.2@2740,2902.87 2740,2723.43 J9.11@2740.19,2723.24
N16801211: C65.1 R56.2 U7.4 | length 197.5
  BOTTOM w6.8: R56.2@2840,2954.05 C65.1@2885,2954.05 2885,3013.37 2892,3020.37 2930,3020.37 2938,3012.37 2938,2978.99 U7.4@2937.6,2978.58
N16801228: R57.1 U7.3 | length 244.1
  BOTTOM w6.8: R57.1@2795,2914.69 2795,2852.37 2807,2840.37 2928,2840.37 2937.6,2849.97 U7.3@2937.6,2880.16
N16802593: D23.1 J11.1 R193.1 | length 465
  BOTTOM w6.8: R193.1@3225,2949.68 3265.32,2949.68 3280,2935 D23.1@3280,2883.74 3328.74,2883.74 3355,2910 3505,2910 3520,2925 J11.1@3520,3020.55
N16803235: R64.1 U8.15 | length 103.4
  TOP w5.2: R64.1@3618.11,2280.32 3633.09,2265.33 3633.09,2216.15 3627.95,2211 U8.15@3627.95,2185.24
N16803237: R65.1 U8.14 | length 103.7
  TOP w5.2: U8.14@3647.64,2185.24 3647.64,2211 3642.49,2216.15 3642.49,2264.7 R65.1@3658.11,2280.32
N16803510: C73.1 U8.3 Y1.1 | length 281.3
  TOP w6.8: Y1.1@3572.83,1790.47 3606.3,1790.47 3611.31,1795.48 3611.31,1923.48 C73.1@3590.11,1944.68 3608.27,1962.84 U8.3@3608.27,2019.88
N16803514: C74.1 U8.4 Y1.3 | length 223.7
  TOP w6.8: U8.4@3627.95,2019.88 3627.95,1963.84 C74.1@3647.11,1944.68 3624.11,1921.68 3624.11,1855.29 3629.87,1849.53 Y1.3@3663.39,1849.53
N16803540: R66.1 U8.13 | length 107.8
  TOP w6.8: U8.13@3667.32,2185.24 3667.32,2249.53 R66.1@3698.11,2280.32
N16803549: C72.1 R61.1 U8.17 | length 156
  TOP w6.8: R61.1@3498.11,2280.32 C72.1@3538.11,2280.32 3588.58,2229.85 U8.17@3588.58,2185.24
N16803553: R63.1 U8.16 | length 107.6
  TOP w6.8: R63.1@3578.11,2280.32 3608.27,2250.16 U8.16@3608.27,2185.24
N16803559: R62.1 U8.18 | length 177.2
  TOP w6.8: R62.1@3458.11,2280.32 3479.31,2259.12 3541.21,2259.12 3568.9,2231.43 U8.18@3568.9,2185.24
N16804913: J12.5 J12.6 L11.2 | length 795
  TOP w20: L11.2@3685,2526.5 3685,2802.64 J12.6@3683.93,2803.7 J12.5@4201.27,2803.7
N16810803: C77.1 R67.2 U9.4 | length 132.7
  TOP w6.8: R67.2@4343.11,1700.32 C77.1@4388.11,1700.32 4388.11,1655 4380.51,1647.4 U9.4@4348.9,1647.4
N16810815: R68.1 U9.3 | length 99.3
  TOP w6.8: R68.1@4443.11,1700.32 4411,1668.21 4411,1653 4416.6,1647.4 U9.3@4447.32,1647.4
N16816847: D33.1 J16.2 R72.1 | length 204.5
  BOTTOM w8: J16.2@3608.58,810 3608.58,889.21 D33.1@3658.11,938.73 3712.52,938.73 R72.1@3713.11,939.32
N16816849: D32.1 J16.1 R71.1 | length 189.5
  BOTTOM w6.8: J16.1@3529.84,810 3529.84,925.47 D32.1@3543.11,938.73 3597.52,938.73 R71.1@3598.11,939.32
N16821329: C87.1 C88.1 C89.1 C90.1 U10.11 | length 231.9
  TOP w6.8: U10.11@1135.73,803.58 1193.42,803.58 1207,790 C89.1@1225.32,790
  TOP w10: v1(1197,830) C90.1@1225.32,830 C89.1@1225.32,790
  BOTTOM w10: v1(1197,830) C88.1@1225.32,830 C87.1@1225.32,790
N16823430: R83.2 R85.1 U10.24 | length 244
  TOP w6.8: R83.2@694.68,930 R85.1@735.32,930 760.32,905 800,905 820,885 881.83,885 891.63,875.2 U10.24@891.63,850.83
N16823432: R83.1 Y2.3 | length 58.2
  TOP w6.8: R83.1@655.32,930 666.72,941.4 Y2.3@666.72,983.47
N16823570: R76.2 U10.8 | length 103.9
  TOP w6.8: U10.8@1135.73,744.53 1172.47,744.53 1207,710 R76.2@1225.32,710
N16823572: R77.2 U10.7 | length 127
  TOP w6.8: U10.7@1135.73,724.84 1171.16,724.84 1188.93,707.07 1188.93,682 1200.93,670 R77.2@1225.32,670
N16823879: R74.2 U10.1 | length 96.5
  TOP w6.8: U10.1@1135.73,606.73 1208.59,606.73 R74.2@1225.32,590
N16823895: R75.2 U10.2 | length 91.1
  TOP w6.8: U10.2@1135.73,626.42 1221.74,626.42 R75.2@1225.32,630
N16825657: D53.1 J26.2 R139.1 | length 156.5
  TOP w6.8: J26.2@2446.85,331.1 v1(2446.85,410)
  BOTTOM w6.8: R139.1@2410,450.32 D53.1@2410,409.68 2410.32,410 v1(2446.85,410)
N16825664: D52.1 J26.3 R140.1 | length 157.8
  TOP w6.8: J26.3@2368.11,331.1 v1(2368.11,410)
  BOTTOM w6.8: R140.1@2330,450.32 D52.1@2330,409.68 2330.32,410 v1(2368.11,410)
N16825671: D51.1 J26.4 R141.1 | length 159
  TOP w6.8: J26.4@2289.37,331.1 v1(2289.37,410)
  BOTTOM w6.8: R141.1@2250,450.32 D51.1@2250,409.68 2250.32,410 v1(2289.37,410)
N16825678: D50.1 J26.5 R142.1 | length 160.3
  TOP w6.8: J26.5@2210.63,331.1 v1(2210.63,410)
  BOTTOM w6.8: R142.1@2170,450.32 D50.1@2170,409.68 2170.32,410 v1(2210.63,410)
N16825685: D49.1 J26.6 R143.1 | length 156.6
  TOP w6.8: J26.6@2131.89,331.1 v1(2131.89,410)
  BOTTOM w6.8: R143.1@2095,450.32 D49.1@2095,409.68 2131.57,409.68 v1(2131.89,410)
N16825692: D48.1 J26.7 R144.1 | length 157.8
  TOP w6.8: J26.7@2053.15,331.1 v1(2053.15,410)
  BOTTOM w6.8: R144.1@2015,450.32 D48.1@2015,409.68 2015.32,410 v1(2053.15,410)
N16827764: D59.1 J27.2 R145.1 | length 192.1
  BOTTOM w6.8: R145.1@4033.11,939.32 D59.1@4078.11,939.32 4078.11,852.91 J27.2@4121.02,810
N16827766: D58.1 J27.3 R146.1 | length 187.4
  BOTTOM w6.8: R146.1@4123.11,939.32 D58.1@4168.11,939.32 4168.11,841.65 J27.3@4199.77,810
N16827768: D57.1 J27.4 R147.1 | length 182.8
  BOTTOM w6.8: R147.1@4213.11,939.32 D57.1@4258.11,939.32 4258.11,830.39 J27.4@4278.51,810
N16827770: D56.1 J27.5 R148.1 | length 178.1
  BOTTOM w6.8: R148.1@4303.11,939.32 D56.1@4348.11,939.32 4348.11,819.13 J27.5@4357.24,810
N16827772: D55.1 J27.6 R149.1 | length 175.2
  BOTTOM w6.8: R149.1@4393.11,939.32 D55.1@4438.11,939.32 4438.11,812.12 J27.6@4435.98,810
N16832694: C114.2 C120.1 U16.2 | length 177.1
  TOP w15.5: U16.2@4419.84,2338.78 C120.1@4419.84,2475.28 4420.12,2475 C114.2@4460.32,2475
N16832701: C114.1 C115.1 CN1.1 | length 85.8
  TOP w15.5: C114.1@4499.68,2475 4539.68,2475 C115.1@4540,2475.32 4540.36,2474.96 CN1.1@4585.24,2474.96
N16832725: R156.2 U16.6 | length 151
  TOP w10: U16.6@4278.11,2338.78 4278.11,2400 4313.11,2435 R156.2@4313.11,2475.32
N16832727: R158.2 U16.7 | length 149.1
  TOP w6.8: U16.7@4242.68,2338.78 4242.68,2409.57 4273.11,2440 R158.2@4273.11,2475.32
N16832815: R164.2 R165.2 U16.12 | length 139.2
  TOP w6.8: R165.2@3942.79,2320 R164.2@3942.79,2280 3943.06,2279.73 U16.12@4041.89,2279.73
N16832856: R166.2 U16.13 | length 100.9
  TOP w6.8: R166.2@3942.79,2240 3947.08,2244.29 U16.13@4041.89,2244.29
N16833042: R162.2 R163.1 Y4.3 | length 95.9
  TOP w6.8: R162.2@4128.11,1700.32 R163.1@4168.11,1700.32 4168.11,1644.8 Y4.3@4168.39,1644.53
N16833048: R162.1 U16.24 | length 130.1
  TOP w6.8: R162.1@4128.11,1739.68 4136.38,1747.95 U16.24@4136.38,1866.34
N16833114: R151.2 R155.1 U16.34 | length 129.3
  TOP w6.8: U16.34@4514.33,1925.39 4603.04,1925.39 R151.2@4603.43,1925 R155.1@4603.43,1965
N16853010: D45.1 D46.1 R130.2 U15.3 | length 246
  BOTTOM w6.8: D45.1@4288.11,2221.42 D46.1@4333.11,2221.42 4341.38,2229.69 R130.2@4378.11,2229.69 4378.11,2153.37 4366.9,2142.16 U15.3@4306.5,2142.16
N16853145: C119.1 U15.2 Y3.2 | length 166.5
  BOTTOM w6.8: Y3.2@4163.11,2143.77 4196.51,2110.37 4218.79,2110.37 C119.1@4233.11,2124.69 4241.22,2116.57 U15.2@4306.5,2116.57
N16853170: C118.1 U15.1 Y3.1 | length 167.8
  BOTTOM w6.8: Y3.1@4163.11,2064.97 4195.71,2097.57 4216.59,2097.57 C118.1@4233.11,2081.05 4243.04,2090.98 U15.1@4306.5,2090.98
N16853193: R131.2 R135.1 U15.7 | length 207.8
  BOTTOM w6.8: R135.1@4458.11,2229.69 R131.2@4418.11,2229.69 4418.1,2128.38 4429.9,2116.57 U15.7@4479.72,2116.57
N16853900: Q1.1 Q2.3 R136.2 | length 248.6
  BOTTOM w15: R136.2@4832.79,1675 4850.61,1692.82 Q1.1@4850.61,1726 4850.61,1793.5 4863.11,1806 Q2.3@4968.11,1806
N16853902: Q2.1 R137.2 R138.1 | length 113.4
  BOTTOM w6.8: R137.2@4987.79,1620 R138.1@4987.79,1675 5005.61,1692.82 Q2.1@5005.61,1726
N16853946: D47.1 J25.1 R134.2 | length 343.2
  BOTTOM w15: R134.2@4853.11,1885 4880.04,1911.93 D47.1@4880.04,1970 4960.11,1970 4975.91,1985.8 J25.1@4975.91,2130.47
N16853981: Q1.2 R132.2 R133.2 R136.1 | length 173.3
  BOTTOM w15: Q1.2@4775.61,1726 4775.61,1692.82 R136.1@4793.43,1675 4781.61,1663.18 R132.2@4781.61,1620 R133.2@4781.61,1565
N16854018: Q1.3 R134.1 | length 113.1
  BOTTOM w15: R134.1@4773.11,1885 4773.11,1816 4783.11,1806 Q1.3@4813.11,1806
N16869660: C151.1 U25.3 | length 73.2
  TOP w6.8: C151.1@4203.31,1037 U25.3@4203.31,1110.2
N16869662: C151.2 U25.1 | length 126.3
  TOP w6.8: U25.1@4103.31,1110.2 4103.31,1049.8 4116.11,1037 C151.2@4163.95,1037
N16869664: C152.1 U25.5 | length 75.9
  TOP w6.8: C152.1@4296.79,1037 4303.31,1043.52 U25.5@4303.31,1110.2
N16869666: C152.2 U25.4 | length 75.1
  TOP w6.8: U25.4@4252.91,1110.2 4252.91,1041.52 C152.2@4257.43,1037
N16869668: C155.1 U25.6 | length 73.2
  TOP w6.8: C155.1@4352.91,1037 U25.6@4352.91,1110.2
N16869670: C154.1 U25.2 | length 272.4
  TOP w6.8: C154.1@4067.79,1037 4067.79,1161.79 4080,1174 4142,1174 4152.91,1163.09 U25.2@4152.91,1110.2
N16869989: D66.1 R119.2 | length 190.9
  BOTTOM w6.8: D66.1@3588.95,345 3730,345 3741,334 R119.2@3741,299.68
N16870097: D54.1 R109.2 | length 198.9
  BOTTOM w6.8: D54.1@4157.95,345 4309,345 4315,339 R109.2@4315,299.68
N16870438: C148.1 U23.3 | length 73.2
  TOP w6.8: C148.1@3666.31,1037 U23.3@3666.31,1110.2
N16870440: C148.2 U23.1 | length 126.9
  TOP w6.8: U23.1@3566.31,1110.2 3566.31,1048.8 3578.11,1037 C148.2@3626.95,1037
N16870442: C149.1 U23.5 | length 75.1
  TOP w6.8: C149.1@3761.79,1037 3766.31,1041.52 U23.5@3766.31,1110.2
N16870444: C149.2 U23.4 | length 75.9
  TOP w6.8: U23.4@3715.91,1110.2 3715.91,1043.52 C149.2@3722.43,1037
N16870446: C147.1 U23.6 | length 73.2
  TOP w6.8: C147.1@3815.91,1037 U23.6@3815.91,1110.2
N16870448: C146.1 U23.2 | length 265.2
  TOP w6.8: C146.1@3533.11,1037 3533.11,1159.2 3545.91,1172 3604.11,1172 3615.91,1160.2 U23.2@3615.91,1110.2
N16880008: C162.1 U27.4 | length 79.2
  TOP w6.8: U27.4@470.79,807.4 v1(511.4,807.4)
  BOTTOM w6.8: v1(511.4,807.4) 528.8,790 C162.1@542.82,790
N16948483: J13.5 J13.6 L12.2 | length 703.8
  TOP w20: J13.6@4351.57,2803.7 J13.5@4868.91,2803.7
  BOTTOM w20: J13.6@4351.57,2803.7 4353.5,2805.63 L12.2@4353.5,2989.37
N16990717: D39.1 J21.1 R98.2 | length 186.6
  TOP w6.8: v1(3165.51,256) J21.1@3165.51,331.1
  BOTTOM w6.8: R98.2@3125,184.68 D39.1@3165,184.68 3165.51,185.19 v1(3165.51,256)
N16990719: D40.1 J21.3 R103.2 | length 187.2
  TOP w6.8: v1(3008.03,256) J21.3@3008.03,331.1
  BOTTOM w6.8: v1(3008.03,256) 3008.03,186.65 D40.1@3010,184.68 R103.2@3050,184.68
N16990803: D41.1 J21.6 R108.2 | length 256.6
  TOP w6.8: v1(2771.81,247) J21.6@2771.81,331.1
  BOTTOM w6.8: v1(2771.81,247) 2771.81,198.28 2785.41,184.68 D41.1@2850,184.68 R108.2@2890,184.68
N16991546: R188.2 U17.21 | length 153.3
  TOP w6.8: R188.2@744.68,1285 778.66,1251.02 U17.21@883.86,1251.02
N17000237: R215.1 U21.4 | length 85.3
  TOP w6.8: U21.4@744.68,1469.76 744.68,1485.68 756,1497 777.32,1497 R215.1@800,1519.68
N17000272: R216.1 U22.4 | length 81.5
  TOP w6.8: U22.4@744.68,1664.76 744.68,1682.68 753,1691 771.32,1691 R216.1@795,1714.68
N17004192: C138.1 C145.1 R179.2 U13.4 U14.4 | length 328.7
  TOP w6.8: U13.4@470.79,522.4 513.03,522.4 v1(515,524.37) ; U14.4@470.79,667.4 513.03,667.4 v1(515,669.37)
  BOTTOM w6.8: v1(515,524.37) 510.63,520 C138.1@479.68,520 R179.2@479.68,560 456.23,583.45 456.23,641.23 479.68,664.68 C145.1@479.68,665 510.63,665 v1(515,669.37)
N17004200: R180.1 U13.3 | length 82.5
  TOP w6.8: U13.3@569.21,522.4 605.4,522.4 v1(611,528)
  BOTTOM w6.8: R180.1@581.68,550 582.4,550 604.4,528 v1(611,528)
N17004297: R181.1 U14.3 | length 72.5
  TOP w6.8: U14.3@569.21,667.4 609.46,667.4 v1(611.43,669.37)
  BOTTOM w6.8: R181.1@582.18,670 610.8,670 v1(611.43,669.37)
N17012559: R239.2 U18.1 | length 250.2
  BOTTOM w6.8: U18.1@4751.57,680 4700,680 4690,670 4690,585 4700,575 R239.2@4785.32,575
N17012562: R240.2 U18.4 | length 233.2
  BOTTOM w6.8: U18.4@4751.57,830 4706.8,830 4700,836.8 4700,927 4708,935 R240.2@4785.32,935
N17015515: R245.2 U19.1 | length 111.2
  BOTTOM w6.8: R245.2@4674.68,1160 4700,1134.68 4700,1115 4710,1105 U19.1@4751.57,1105
N17015527: R246.2 U19.4 | length 108.3
  BOTTOM w6.8: R246.2@4674.68,1200 4705,1230.32 4705,1245 4715,1255 U19.4@4751.57,1255
ON/OFF_KEY: D46.2 J3.11 R71.2 | length 3872.7
  TOP w6.8: J3.11@3310.59,960.59 3356.67,960.59 v1(3364.54,952.72)
  ART03 w6.3: v1(3364.54,952.72) 3418.51,952.72 3431.11,965.32 3431.11,1015.4 3443.71,1028 3575.59,1028 3597.59,1006 v1(3598.11,1006) 3598.11,976.89 3613,962 3741.11,962 3756.11,977 3756.11,1042 3769.11,1055 4471,1055 4487,1071 4487,1437.4 4499.6,1450 4702.14,1450 v1(4720.71,1468.58)
  BOTTOM w6.8: R71.2@3598.11,978.68 v1(3598.11,1006) ; D46.2@4333.11,2277.32 4333.11,2324.89 4312.63,2345.37 4071.37,2345.37 4052,2326 4052,1984 4064.2,1971.8 4674.2,1971.8 4740.11,1905.89 4740.11,1675.89 4754,1662 4754,1501.87 v1(4720.71,1468.58)
PCM_CLK: R160.1 U16.26 | length 260.2
  TOP w6.8: U16.26@4207.24,1866.34 4207.24,1804.87 4254.69,1757.42 4254.69,1656.26 R160.1@4233.11,1634.68
PCM_DIN: R159.1 U16.27 | length 143.4
  TOP w6.8: U16.27@4242.68,1866.34 4242.68,1808.43 4283.11,1768 R159.1@4283.11,1739.68
PCM_OUT: R161.1 U16.25 | length 152.1
  TOP w6.8: U16.25@4171.81,1866.34 4171.81,1800.98 R161.1@4233.11,1739.68
PCM_SYNC: R157.1 U16.28 | length 253.6
  TOP w6.8: U16.28@4278.11,1866.34 4278.11,1809 4307.11,1780 4307.11,1658.68 R157.1@4283.11,1634.68
PWM3_IR: J3.199 R108.1 | length 801.3
  TOP w6.8: v1(2890,116) 2924,82 3192.63,82 3206.23,95.6 3206.23,467.77 3196.42,477.58 J3.199@3196.42,527.52
  BOTTOM w6.8: v1(2890,116) R108.1@2890,145.32
RECOVERY/ADC_KEY: D34.1 J3.35 J16.3 | length 3038
  TOP w6.8: J3.35@3310.59,1810.98 3358.65,1810.98 v1(3369.63,1800)
  ART03 w6.3: v1(3803.38,938.73) 3803.38,1008.27 3823.11,1028 4460.51,1028 v1(4476.51,1012)
  BOTTOM w6.8: v1(3369.63,1800) 3389.63,1780 3759,1780 3787,1752 3908,1752 3934.23,1725.77 4163.77,1725.77 4203.8,1765.8 4305.05,1765.8 4339.65,1731.2 4540.31,1731.2 4566.85,1704.65 4566.85,1687.76 4566.85,1609.29 4528.11,1570.55 4528.11,1323.11 4476.51,1271.51 v1(4476.51,1012) ; J16.3@3687.32,810 3687.32,891.21 3697.11,901 3730.38,901 D34.1@3768.11,938.73 v1(3803.38,938.73)
RESET_KEY: J3.12 R72.2 | length 515.6
  TOP w6.8: J3.12@3310.59,996.02 3360.61,996.02 v1(3364.54,992.09)
  ART03 w8: v1(3364.54,992.09) 3391.09,992.09 3403.11,1004.11 3403.11,1039.4 3415.71,1052 3700.51,1052 3713.11,1039.4 v1(3713.11,1005)
  BOTTOM w6.8: R72.2@3713.11,978.68 v1(3713.11,1005)
RS232_1_3V3: C144.1 J32.1 J34.1 L14.1 U23.16 | length 1392
  TOP w15: v1(3467.11,1286) L14.1@3467.11,1251.5 3478.93,1239.68 C144.1@3517.11,1239.68 3552.79,1239.68 3566.31,1253.2 U23.16@3566.31,1329.8 ; J32.1@3529.84,545 3529.84,504 3559.84,474 3623,474 3647.95,449.05 J34.1@3647.95,331.1
  BOTTOM w15: v1(3467.11,1286) 3427,1286 3402,1261 3402,885 3417,870 3463.11,870 3478.11,855 3478.11,596.73 J32.1@3529.84,545
RS232_1_R1IN: J34.3 R116.2 U23.13 | length 1807.4
  TOP w10: J34.3@3490.47,331.1 3490.47,415.53 3454.11,451.89 3454.11,944.11 3478.79,968.79 v1(3493.75,968.79) ; R116.2@3560.91,1492.68 v1(3560.91,1523) ; v1(3715.91,1270.2) U23.13@3715.91,1329.8
  ART03 w10: v1(3560.91,1523) 3560.91,1244 3576.91,1228 3699.91,1228 3715.91,1244 v1(3715.91,1270.2)
  BOTTOM w10: v1(3493.75,968.79) 3471.11,968.79 3461.11,978.79 3461.11,1071 3473.11,1083 3699.11,1083 3715.91,1099.8 v1(3715.91,1270.2)
RS232_1_R2IN: J32.3 R113.2 U23.8 | length 1193.4
  TOP w10: J32.3@3687.32,545 3687.32,635.21 3698.11,646 3817.11,646 3840.11,669 3840.11,880 3915.91,955.8 U23.8@3915.91,1110.2 v1(3915.91,1168) ; R113.2@3865.91,1492.68 v1(3865.91,1523)
  ART03 w10: v1(3865.91,1523) 3894.11,1494.8 3894.11,1189.8 v1(3915.91,1168)
RS232_1_T1OUT: J34.2 R118.2 U23.14 | length 1638
  TOP w10: v1(3493.75,929.42) 3483.11,918.78 3483.11,469.89 3509,444 3551,444 3569.21,425.79 J34.2@3569.21,331.1 ; R118.2@3660.91,1492.68 v1(3660.91,1523) ; v1(3666.31,1270.2) U23.14@3666.31,1329.8
  ART03 w10: v1(3660.91,1523) 3629.11,1491.2 3629.11,1307.4 v1(3666.31,1270.2)
  BOTTOM w10: v1(3493.75,929.42) 3447.69,929.42 3433.11,944 3433.11,1090 3458.11,1115 3653.11,1115 3666.31,1128.2 v1(3666.31,1270.2)
RS232_1_T2OUT: J32.2 R114.2 U23.7 | length 1299.9
  TOP w10: J32.2@3608.58,545 3608.58,657.47 3629.11,678 3791.11,678 3810.11,697 3810.11,891 3880.11,961 3880.11,1051.32 3866.31,1065.12 U23.7@3866.31,1110.2 v1(3866.31,1168) ; R114.2@3761.91,1492.68 v1(3761.91,1523)
  ART03 w10: v1(3761.91,1523) 3790.11,1494.8 3790.11,1184 3806.11,1168 v1(3866.31,1168)
RS232_2_3V3: C150.1 J35.1 J37.1 L16.1 U25.16 | length 1346.8
  TOP w15: v1(3915.91,1246.74) 3920.67,1251.5 L16.1@3986,1251.5 3997.82,1239.68 C150.1@4040,1239.68 4084.68,1239.68 4103.31,1258.31 U25.16@4103.31,1329.8 ; J35.1@3943.55,545 3995.55,493 4113,493 4130.39,475.61 J37.1@4130.39,331.1
  BOTTOM w15: v1(3915.91,1246.74) 3942,1220.65 3942,546.54 J35.1@3943.55,545
RS232_2_R1IN: J37.3 R126.2 U25.13 | length 2196.7
  TOP w10: J37.3@3972.91,331.1 3972.91,412.09 3953,432 3904.11,432 3870.11,466 3870.11,868 3969.22,967.11 v1(3993.74,967.11) ; R126.2@4104.11,1492.68 v1(4104.11,1523) ; v1(4252.91,1270.2) U25.13@4252.91,1329.8
  ART03 w10: v1(4104.11,1523) 4104.11,1477 4121.11,1460 4234.11,1460 4252.91,1441.2 v1(4252.91,1270.2)
  BOTTOM w10: v1(3993.74,967.11) 3993.74,1226.4 4007.34,1240 4222.71,1240 v1(4252.91,1270.2) 4254,1271.29 4254,1455 4232,1477 4232,1529 4211,1550 4130,1550 4104.11,1524.11 v1(4104.11,1523)
RS232_2_R2IN: J35.3 R123.2 U25.8 | length 1602.5
  TOP w10: J35.3@4101.02,545 4101.02,658.09 4077.11,682 3990.11,682 3969.11,703 3969.11,831 3998.11,860 4426.78,860 4452.91,886.13 U25.8@4452.91,1110.2 v1(4452.91,1168) ; R123.2@4404.11,1492.68 v1(4404.11,1523)
  ART03 w10: v1(4404.11,1523) 4432.91,1523 4452.91,1503 v1(4452.91,1168)
RS232_2_T1OUT: J37.2 R128.2 U25.14 | length 1731.3
  TOP w10: v1(3993.74,927.74) 3972.85,927.74 3897.11,852 3897.11,482 3916.11,463 4037,463 4051.65,448.35 J37.2@4051.65,331.1 ; v1(4203.31,1270.2) U25.14@4203.31,1329.8 ; R128.2@4204.11,1492.68 v1(4204.11,1523)
  BOTTOM w10: v1(3993.74,927.74) 3971,950.48 3971,1257 3984.2,1270.2 v1(4203.31,1270.2) 4238,1304.89 4238,1442 4204.11,1475.89 v1(4204.11,1523)
RS232_2_T2OUT: J35.2 R124.2 U25.7 | length 1565.5
  TOP w10: J35.2@4022.28,545 4022.28,620.83 3999.11,644 3957.11,644 3937.11,664 3937.11,846 3982.11,891 4406.11,891 4421.11,906 4421.11,1048 4403.31,1065.8 U25.7@4403.31,1110.2 v1(4403.31,1168) ; R124.2@4304.11,1492.68 v1(4304.11,1523)
  ART03 w10: v1(4304.11,1523) 4333.11,1494 4333.11,1428.89 4384,1378 4384,1187.31 v1(4403.31,1168)
RS485_1_3V3: C153.1 D54.2 J33.1 L15.2 U24.8 | length 1188.7
  TOP w15: v1(4612.83,245) J33.1@4612.83,331.1
  BOTTOM w15: U24.8@4228.43,125 4177,125 4165.32,113.32 C153.1@4165.32,65 L15.2@4106.5,65 4106.5,340.55 D54.2@4102.05,345 4136.05,379 4590,379 4613,356 4613,245.17 v1(4612.83,245)
RS485_1_A: J33.3 R109.1 R110.2 R115.2 U24.6 | length 952.5
  TOP w10: v1(3863,180) 3870.37,180 3897.37,153 4183,153 4194,164 4194,204 v1(4173,225) ; v1(4455.35,245) J33.3@4455.35,331.1
  BOTTOM w10: v1(3863,180) R115.2@3890.32,180 ; v1(4173,225) U24.6@4228.43,225 4309.68,225 R110.2@4315,219.68 ; R109.1@4315,260.32 R110.2@4315,219.68 ; v1(4455.35,245) 4479,245 4489,235 4489,218 4479,208 4326.68,208 R110.2@4315,219.68
RS485_1_B: J33.2 R110.1 R112.1 R117.2 U24.7 | length 1080.7
  TOP w10: v1(3823,345) 3848,320 3848,225 3904,169 4167,169 v1(4173,175) ; v1(4534.09,245) J33.2@4534.09,331.1
  BOTTOM w10: v1(3823,345) R117.2@3890.32,345 ; v1(4173,175) U24.7@4228.43,175 4309.68,175 R110.1@4315,180.32 ; R112.1@4315,139.68 R110.1@4315,180.32 ; v1(4534.09,245) 4512.09,245 4505,237.91 4505,211.37 4485.63,192 4327,192 4315.32,180.32 R110.1@4315,180.32
RS485_1_DIR: J3.62 R111.1 U24.2 U24.3 | length 3619
  TOP w6.8: v1(2769.86,2333.28) 2778.28,2333.28 2798,2353 2828,2353 2842.09,2367.09 J3.62@2842.09,2421.22
  ART03 w6.3: v1(2769.86,2333.28) 2795,2308.14 2795,482.6 2807.6,470 3261,470 3275,456 3275,422.6 3287.6,410 3834.88,410 3847.48,397.4 3847.48,287.74 3826,266.26 v1(3823,266.26)
  BOTTOM w6.8: v1(3823,266.26) 3834.11,255.15 3916.35,255.15 R111.1@3941.5,230
  BOTTOM w10: R111.1@3941.5,230 3946.5,225 U24.3@4031.57,225 4074,225 4082,217 4082,183 4074,175 U24.2@4031.57,175
RS485_2_3V3: C156.1 D66.2 J36.1 L17.2 U26.8 | length 1438.5
  BOTTOM w15: U26.8@3659.43,125 3600,125 3590.32,115.32 C156.1@3590.32,65 L17.2@3531.5,65 3533.05,66.55 D66.2@3533.05,345 3533.05,462.05 3562,491 4303.25,491 J36.1@4357.25,545
RS485_2_A: J36.3 R119.1 R120.2 R125.2 U26.6 | length 2138.5
  TOP w10: v1(3295,180) 3558.72,180 3584.72,154 3613,154 3623,164 3623,204 v1(3602,225)
  BOTTOM w6.8: R120.2@3741,219.68 R120.2@3741.32,219.68
  BOTTOM w10: v1(3295,180) R125.2@3326.32,180 ; v1(3602,225) U26.6@3659.43,225 3735.68,225 R120.2@3741,219.68 R119.1@3741,260.32 ; R120.2@3741.32,219.68 3753,208 3771,208 3777,214 3777,430.63 3804.37,458 4611,458 4631,478 4631,617 4621,627 4498,627 4481,610 4481,578.73 J36.3@4514.73,545
RS485_2_B: J36.2 R120.1 R122.1 R127.2 U26.7 | length 2260.2
  TOP w10: v1(3295,345) 3298,342 3298,213 3315,196 3566,196 3587,175 v1(3602,175)
  BOTTOM w10: v1(3295,345) R127.2@3326.32,345 ; v1(3602,175) U26.7@3659.43,175 3735.68,175 R120.1@3741,180.32 ; R122.1@3741,139.68 R120.1@3741,180.32 ; J36.2@4435.99,545 4465,574.01 4465,616.63 4491.37,643 4630.63,643 4647,626.63 4647,468.37 4620.63,442 3811,442 3793,424 3793,207 3778,192 3752.68,192 R120.1@3741,180.32
RS485_2_DIR: J3.61 R121.1 U26.2 U26.3 | length 3120.1
  TOP w6.8: v1(2809.23,2333.28) 2863.92,2333.28 2877.52,2346.88 J3.61@2877.52,2421.22
  ART03 w6.3: v1(2809.23,2333.28) 2815,2327.51 2815,502.6 2827.6,490 3283,490 3300,473 v1(3300,449.68)
  BOTTOM w6.8: v1(3300,449.68) 3300,396 3292,388 3258,388 3230,360 3230,271.8 3242.8,259 3348.5,259 R121.1@3377.5,230
  BOTTOM w10: R121.1@3377.5,230 3382.5,225 U26.3@3462.57,225 3504,225 3512,217 3512,183 3504,175 U26.2@3462.57,175
RTC_INT: D45.2 J3.197 | length 2821.5
  TOP w6.8: J3.197@3125.55,527.52 3125.55,604.4 3139.15,618 3193.4,618 3207,631.6 3207,1969.52 v1(3229.85,1992.37)
  ART03 w6.3: v1(3229.85,1992.37) 3229.85,2104.85 3244,2119 3569,2119 3582,2106 3675,2106 3739,2170 3864,2170 3884,2190 3884,2214 3899,2229 3899,2254 3917,2272 v1(4093.11,2272)
  BOTTOM w6.8: v1(4093.11,2272) 4098.43,2277.32 D45.2@4288.11,2277.32
SARADC0_BOOT: J3.36 R261.1 | length 2807.3
  TOP w6.8: R261.1@1255,1614.68 1340.32,1614.68 1356,1599 v1(1356,1358) ; v1(3260,1846.42) J3.36@3310.59,1846.42
  BOTTOM w6.8: v1(1356,1358) 1356,1399.4 1369.6,1413 1506,1413 1535,1384 1972.98,1384 1986.58,1397.6 1986.58,1830.58 1999.6,1843.6 3195.45,1843.6 3198.27,1846.42 v1(3260,1846.42)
